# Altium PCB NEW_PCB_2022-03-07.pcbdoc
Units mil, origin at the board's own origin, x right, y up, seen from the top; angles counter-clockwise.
Board outline 1355.38 x 1257.38 mil, 2 copper layers (Top Layer, Bottom Layer); 1 components, 0 nets, 29 pads, 0 vias.
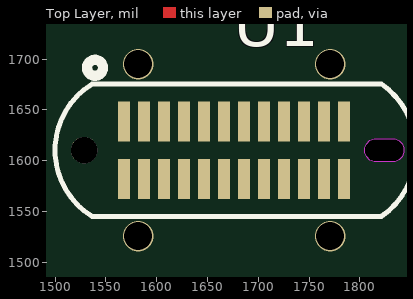
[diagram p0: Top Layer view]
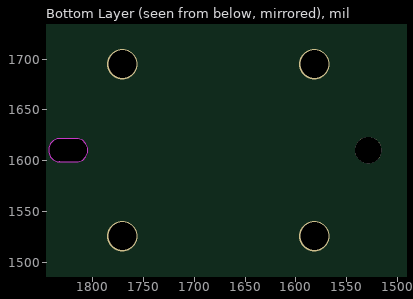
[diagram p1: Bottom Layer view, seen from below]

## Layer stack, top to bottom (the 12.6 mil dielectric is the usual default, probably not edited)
Top Solder: solder mask 0.4, Solder Resist, Dk 3.5
Top Layer: signal copper 1.4
Dielectric1: dielectric 12.6, FR-4, Dk 4.8
Bottom Layer: signal copper 1.4
Bottom Solder: solder mask 0.4, Solder Resist, Dk 3.5

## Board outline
2355.38,1000 1000,1000 1000,2257.38 2355.38,2257.38

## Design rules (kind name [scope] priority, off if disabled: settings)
Clearance [All] p1: gap=10 ignorepadtopadclearanceinfootprint=FALSE except(0: Arc-Hole Track-Hole SMDPad-Hole THPad-Hole Via-Hole Fill-Hole Poly-Hole Region-Hole Text-Hole)
PolygonConnect [All] p1: connectstyle=Relief reliefconductorwidth=10 reliefentries=4 polygonreliefangle="90 Angle" airgapwidth=10
RoutingVias [All] p1: holewidth=28 width=50 viastyle="Through Hole" minholewidth=28 minwidth=50 maxholewidth=28 maxwidth=50
SolderMaskExpansion [All] p1: expansion=4
Width [All] p1: maxlimit=10 minlimit=10 preferedwidth=10
30 further rules are at their usual default settings.

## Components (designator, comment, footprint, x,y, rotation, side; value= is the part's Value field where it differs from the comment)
U1 "USB-C-SMD_TYPEC-501S-ACP24H104" USB-C-SMD_TYPEC-501S-ACP24H104 1676.32,1610.24 r0 top

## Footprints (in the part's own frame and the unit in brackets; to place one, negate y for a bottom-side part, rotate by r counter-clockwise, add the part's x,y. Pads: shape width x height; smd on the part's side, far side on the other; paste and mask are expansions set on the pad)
USB-C-SMD_TYPEC-501S-ACP24H104 [mm]
  round 0.762 hole 0.7: 0(-2.4,-2.15) 0(-2.4,2.15) 0(2.4,-2.15) 0(2.4,2.15)
  rect 0.3x1 smd: A1(-2.75,0.72) A2(-2.25,0.72) A3(-1.75,0.72) A4(-1.25,0.72) A5(-0.75,0.72) A6(-0.25,0.72) A7(0.25,0.72) A8(0.75,0.72) A9(1.25,0.72) A10(1.75,0.72) A11(2.25,0.72) A12(2.75,0.72) B1(2.75,-0.72) B2(2.25,-0.72) B3(1.75,-0.72) B4(1.25,-0.72) B5(0.75,-0.72) B6(0.25,-0.72) B7(-0.25,-0.72) B8(-0.75,-0.72) B9(-1.25,-0.72) B10(-1.75,-0.72) B11(-2.25,-0.72) B12(-2.75,-0.72)
  round 0.66 hole 0.66 unplated: ""(-3.75,0)
  Keep-Out Layer board cut-out: 3.97,-0.29 3.968,-0.29 3.968,-0.29 3.968,-0.29 3.968,-0.29 3.968,-0.29 3.968,-0.29 3.968,-0.29 3.968,-0.29
  Keep-Out Layer board cut-out: 4.244,0 4.244,-0.056 4.203,-0.16 4.126,-0.241 4.024,-0.287 3.968,-0.29 3.968,-0.29 3.968,-0.29 3.556,-0.29 3.499,-0.289 3.393,-0.245 3.312,-0.163 3.268,-0.057 3.268,0 3.268,0 3.268,0 3.268,0.058 3.312,0.164 3.393,0.245 3.499,0.29 3.556,0.29 3.556,0.29 3.556,0.29 3.97,0.29 4.026,0.287 4.127,0.24 4.203,0.159 4.244,0.056 4.244,0 4.244,0 4.244,0
  silkscreen extent -4.48,-1.65 4.55,2.26

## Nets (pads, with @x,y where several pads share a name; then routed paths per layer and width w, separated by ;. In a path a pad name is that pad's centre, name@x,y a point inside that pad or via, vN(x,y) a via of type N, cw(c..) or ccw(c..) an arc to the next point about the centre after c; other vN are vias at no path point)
pads on no net: U1. U1.0 U1.A1 U1.A2 U1.A3 U1.A4 U1.A5 U1.A6 U1.A7 U1.A8 U1.A9 U1.A10 U1.A11 U1.A12 U1.B1 U1.B2 U1.B3 U1.B4 U1.B5 U1.B6 U1.B7 U1.B8 U1.B9 U1.B10 U1.B11 U1.B12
